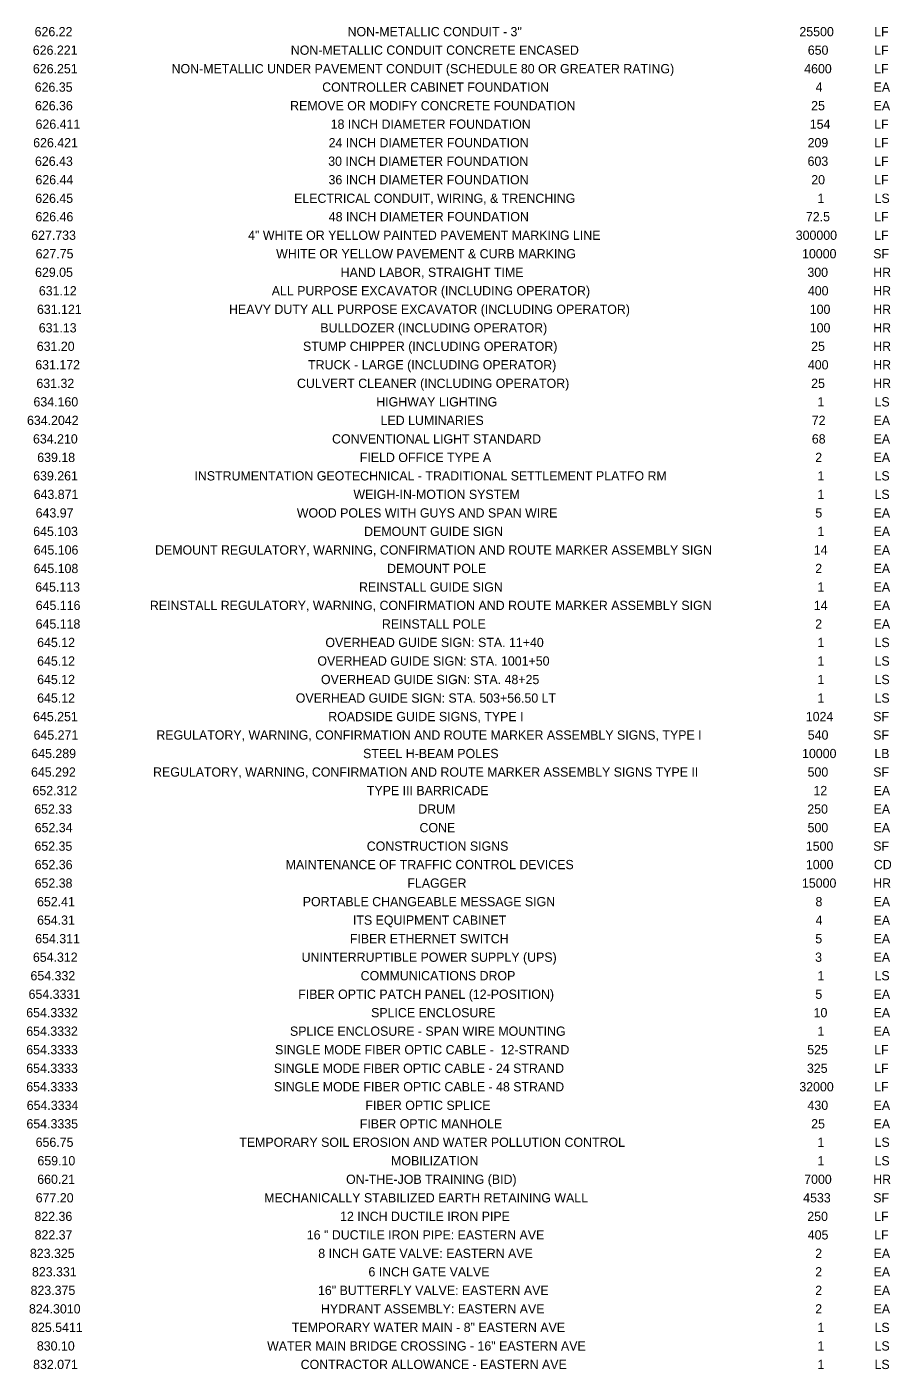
# Model space of a CAD drawing. Extents: x -18.7 to 5.6, y -2.7 to 4.
# Drawn here: x -18.677 to -17.757, y -1.71 to -0.282 of the extents above; entities that cross this region are included whole.
import ezdxf

# ---------------------------------------------------------------- set-up
doc = ezdxf.new("R2010")
doc.units = 0
doc.layers.add('ANNOTATION', color=7, linetype='Continuous')

msp = doc.modelspace()

# ---------------------------------------------------------------- texts
at = {"layer": 'ANNOTATION'}
for s, height, p in [('626.22', 0.00984, (-18.6685, -0.2925)), ('NON-METALLIC CONDUIT - 3"', 0.009843, (-18.3356, -0.2925)), ('25500', 0.00984, (-17.855, -0.2925)), ('LF', 0.00984, (-17.7755, -0.2925)), ('626.221', 0.00984, (-18.6704, -0.3122)), ('NON-METALLIC CONDUIT CONCRETE ENCASED', 0.009843, (-18.396, -0.3122)), ('650', 0.00984, (-17.8461, -0.3122)), ('LF', 0.00984, (-17.7755, -0.3122)), ('626.251', 0.00984, (-18.6703, -0.3319)), ('NON-METALLIC UNDER PAVEMENT CONDUIT (SCHEDULE 80 OR GREATER RATING)', 0.009843, (-18.5228, -0.3319)), ('4600', 0.00984, (-17.8499, -0.3319)), ('LF', 0.00984, (-17.7755, -0.3319)), ('626.35', 0.00984, (-18.6684, -0.3515)), ('CONTROLLER CABINET FOUNDATION', 0.009843, (-18.3626, -0.3515)), ('4', 0.00984, (-17.8378, -0.3515)), ('EA', 0.00984, (-17.7761, -0.3515)), ('626.36', 0.00984, (-18.6681, -0.3712)), ('REMOVE OR MODIFY CONCRETE FOUNDATION', 0.009843, (-18.3967, -0.3712)), ('25', 0.00984, (-17.8425, -0.3712)), ('EA', 0.00984, (-17.7761, -0.3712)), ('626.411', 0.00984, (-18.6675, -0.3909)), ('18 INCH DIAMETER FOUNDATION', 0.009843, (-18.3536, -0.3909)), ('154', 0.00984, (-17.844, -0.3909)), ('LF', 0.00984, (-17.7755, -0.3909)), ('626.421', 0.00984, (-18.67, -0.4106)), ('24 INCH DIAMETER FOUNDATION', 0.009843, (-18.3558, -0.4106)), ('209', 0.00984, (-17.8463, -0.4106)), ('LF', 0.00984, (-17.7755, -0.4106)), ('626.43', 0.00984, (-18.6681, -0.4303)), ('30 INCH DIAMETER FOUNDATION', 0.009843, (-18.3562, -0.4303)), ('603', 0.00984, (-17.8463, -0.4303)), ('LF', 0.00984, (-17.7755, -0.4303)), ('626.44', 0.00984, (-18.6676, -0.45)), ('36 INCH DIAMETER FOUNDATION', 0.009843, (-18.3559, -0.45)), ('20', 0.00984, (-17.8424, -0.45)), ('LF', 0.00984, (-17.7755, -0.45)), ('626.45', 0.00984, (-18.6678, -0.4697)), ('ELECTRICAL CONDUIT, WIRING, & TRENCHING', 0.009843, (-18.3925, -0.4697)), ('1', 0.00984, (-17.8358, -0.4697)), ('LS', 0.00984, (-17.7751, -0.4697)), ('626.46', 0.00984, (-18.6676, -0.4893)), ('48 INCH DIAMETER FOUNDATION', 0.009843, (-18.3556, -0.4893)), ('72.5', 0.00984, (-17.8481, -0.4893)), ('LF', 0.00984, (-17.7755, -0.4893)), ('627.733', 0.00984, (-18.6721, -0.509)), ('4" WHITE OR YELLOW PAINTED PAVEMENT MARKING LINE', 0.009843, (-18.4414, -0.509)), ('300000', 0.00984, (-17.8589, -0.509)), ('LF', 0.00984, (-17.7755, -0.509)), ('627.75', 0.00984, (-18.6674, -0.5287)), ('WHITE OR YELLOW PAVEMENT & CURB MARKING', 0.009843, (-18.4116, -0.5287)), ('10000', 0.00984, (-17.8522, -0.5287)), ('SF', 0.00984, (-17.7765, -0.5287)), ('629.05', 0.00984, (-18.668, -0.5484)), ('HAND LABOR, STRAIGHT TIME', 0.009843, (-18.343, -0.5484)), ('300', 0.00984, (-17.8465, -0.5484)), ('HR', 0.00984, (-17.7765, -0.5484)), ('631.12', 0.00984, (-18.664, -0.5681)), ('ALL PURPOSE EXCAVATOR (INCLUDING OPERATOR)', 0.009843, (-18.4163, -0.5681)), ('400', 0.00984, (-17.846, -0.5681)), ('HR', 0.00984, (-17.7765, -0.5681)), ('631.121', 0.00984, (-18.666, -0.5878)), ('HEAVY DUTY ALL PURPOSE EXCAVATOR (INCLUDING OPERATOR)', 0.009843, (-18.4617, -0.5878)), ('100', 0.00984, (-17.844, -0.5878)), ('HR', 0.00984, (-17.7765, -0.5878)), ('631.13', 0.00984, (-18.6641, -0.6075)), ('BULLDOZER (INCLUDING OPERATOR)', 0.009843, (-18.3646, -0.6075)), ('100', 0.00984, (-17.844, -0.6075)), ('HR', 0.00984, (-17.7765, -0.6075)), ('631.20', 0.00984, (-18.6662, -0.6271)), ('STUMP CHIPPER (INCLUDING OPERATOR)', 0.009843, (-18.383, -0.6271)), ('25', 0.00984, (-17.8425, -0.6271)), ('HR', 0.00984, (-17.7765, -0.6271)), ('631.172', 0.00984, (-18.6678, -0.6468)), ('TRUCK - LARGE (INCLUDING OPERATOR)', 0.009843, (-18.3776, -0.6468)), ('400', 0.00984, (-17.846, -0.6468)), ('HR', 0.00984, (-17.7765, -0.6468)), ('631.32', 0.00984, (-18.6666, -0.6665)), ('CULVERT CLEANER (INCLUDING OPERATOR)', 0.009843, (-18.3894, -0.6665)), ('25', 0.00984, (-17.8425, -0.6665)), ('HR', 0.00984, (-17.7765, -0.6665)), ('634.160', 0.00984, (-18.6697, -0.6862)), ('HIGHWAY LIGHTING', 0.009843, (-18.3051, -0.6862)), ('1', 0.00984, (-17.8358, -0.6862)), ('LS', 0.00984, (-17.7751, -0.6862)), ('634.2042', 0.00984, (-18.6766, -0.7059)), ('LED LUMINARIES', 0.009843, (-18.3005, -0.7059)), ('72', 0.00984, (-17.8419, -0.7059)), ('EA', 0.00984, (-17.7761, -0.7059)), ('634.210', 0.00984, (-18.6702, -0.7256)), ('CONVENTIONAL LIGHT STANDARD', 0.009843, (-18.3521, -0.7256)), ('68', 0.00984, (-17.8418, -0.7256)), ('EA', 0.00984, (-17.7761, -0.7256)), ('639.18', 0.00984, (-18.6657, -0.7453)), ('FIELD OFFICE TYPE A', 0.009843, (-18.3226, -0.7453)), ('2', 0.00984, (-17.8382, -0.7453)), ('EA', 0.00984, (-17.7761, -0.7453)), ('639.261', 0.00984, (-18.67, -0.7649)), ('INSTRUMENTATION GEOTECHNICAL - TRADITIONAL SETTLEMENT PLATFO RM', 0.009843, (-18.4985, -0.7649)), ('1', 0.00984, (-17.8358, -0.7649)), ('LS', 0.00984, (-17.7751, -0.7649)), ('643.871', 0.00984, (-18.6695, -0.7846)), ('WEIGH-IN-MOTION SYSTEM', 0.009843, (-18.3294, -0.7846)), ('1', 0.00984, (-17.8358, -0.7846)), ('LS', 0.00984, (-17.7751, -0.7846)), ('643.97', 0.00984, (-18.6674, -0.8043)), ('WOOD POLES WITH GUYS AND SPAN WIRE', 0.009843, (-18.3896, -0.8043)), ('5', 0.00984, (-17.8381, -0.8043)), ('EA', 0.00984, (-17.7761, -0.8043)), ('645.103', 0.00984, (-18.67, -0.824)), ('DEMOUNT GUIDE SIGN', 0.009843, (-18.318, -0.824)), ('1', 0.00984, (-17.8358, -0.824)), ('EA', 0.00984, (-17.7761, -0.824)), ('645.106', 0.00984, (-18.6695, -0.8437)), ('DEMOUNT REGULATORY, WARNING, CONFIRMATION AND ROUTE MARKER ASSEMBLY SIGN', 0.009843, (-18.5404, -0.8437)), ('14', 0.00984, (-17.8397, -0.8437)), ('EA', 0.00984, (-17.7761, -0.8437)), ('645.108', 0.00984, (-18.6696, -0.8634)), ('DEMOUNT POLE', 0.009843, (-18.2936, -0.8634)), ('2', 0.00984, (-17.8382, -0.8634)), ('EA', 0.00984, (-17.7761, -0.8634)), ('645.113', 0.00984, (-18.6678, -0.8831)), ('REINSTALL GUIDE SIGN', 0.009843, (-18.3234, -0.8831)), ('1', 0.00984, (-17.8358, -0.8831)), ('EA', 0.00984, (-17.7761, -0.8831)), ('645.116', 0.00984, (-18.6673, -0.9027)), ('REINSTALL REGULATORY, WARNING, CONFIRMATION AND ROUTE MARKER ASSEMBLY SIGN', 0.009843, (-18.5459, -0.9027)), ('14', 0.00984, (-17.8397, -0.9027)), ('EA', 0.00984, (-17.7761, -0.9027)), ('645.118', 0.00984, (-18.6674, -0.9224)), ('REINSTALL POLE', 0.009843, (-18.2991, -0.9224)), ('2', 0.00984, (-17.8382, -0.9224)), ('EA', 0.00984, (-17.7761, -0.9224)), ('645.12', 0.00984, (-18.6658, -0.9421)), ('OVERHEAD GUIDE SIGN: STA. 11+40', 0.009843, (-18.3592, -0.9421)), ('1', 0.00984, (-17.8358, -0.9421)), ('LS', 0.00984, (-17.7751, -0.9421)), ('645.12', 0.00984, (-18.6658, -0.9618)), ('OVERHEAD GUIDE SIGN: STA. 1001+50', 0.009843, (-18.3677, -0.9618)), ('1', 0.00984, (-17.8358, -0.9618)), ('LS', 0.00984, (-17.7751, -0.9618)), ('645.12', 0.00984, (-18.6658, -0.9815)), ('OVERHEAD GUIDE SIGN: STA. 48+25', 0.009843, (-18.3639, -0.9815)), ('1', 0.00984, (-17.8358, -0.9815)), ('LS', 0.00984, (-17.7751, -0.9815)), ('645.12', 0.00984, (-18.6658, -1.0012)), ('OVERHEAD GUIDE SIGN: STA. 503+56.50 LT', 0.009843, (-18.3907, -1.0012)), ('1', 0.00984, (-17.8358, -1.0012)), ('LS', 0.00984, (-17.7751, -1.0012)), ('645.251', 0.00984, (-18.6701, -1.0209)), ('ROADSIDE GUIDE SIGNS, TYPE I', 0.009843, (-18.3562, -1.0209)), ('1024', 0.00984, (-17.8482, -1.0209)), ('SF', 0.00984, (-17.7765, -1.0209)), ('645.271', 0.00984, (-18.6696, -1.0405)), ('REGULATORY, WARNING, CONFIRMATION AND ROUTE MARKER ASSEMBLY SIGNS, TYPE I', 0.009843, (-18.539, -1.0405)), ('540', 0.00984, (-17.8461, -1.0405)), ('SF', 0.00984, (-17.7765, -1.0405)), ('645.289', 0.00984, (-18.672, -1.0602)), ('STEEL H-BEAM POLES', 0.009843, (-18.3191, -1.0602)), ('10000', 0.00984, (-17.8522, -1.0602)), ('LB', 0.00984, (-17.7753, -1.0602)), ('645.292', 0.00984, (-18.6723, -1.0799)), ('REGULATORY, WARNING, CONFIRMATION AND ROUTE MARKER ASSEMBLY SIGNS TYPE II', 0.009843, (-18.5425, -1.0799)), ('500', 0.00984, (-17.8463, -1.0799)), ('SF', 0.00984, (-17.7765, -1.0799)), ('652.312', 0.00984, (-18.6708, -1.0996)), ('TYPE III BARRICADE', 0.009843, (-18.3151, -1.0996)), ('12', 0.00984, (-17.8401, -1.0996)), ('EA', 0.00984, (-17.7761, -1.0996)), ('652.33', 0.00984, (-18.6689, -1.1193)), ('DRUM', 0.00984, (-18.2604, -1.1193)), ('250', 0.00984, (-17.8466, -1.1193)), ('EA', 0.00984, (-17.7761, -1.1193)), ('652.34', 0.00984, (-18.6684, -1.139)), ('CONE', 0.00984, (-18.2591, -1.139)), ('500', 0.00984, (-17.8463, -1.139)), ('EA', 0.00984, (-17.7761, -1.139)), ('652.35', 0.00984, (-18.6687, -1.1587)), ('CONSTRUCTION SIGNS', 0.009843, (-18.3152, -1.1587)), ('1500', 0.00984, (-17.8482, -1.1587)), ('SF', 0.00984, (-17.7765, -1.1587)), ('652.36', 0.00984, (-18.6684, -1.1783)), ('MAINTENANCE OF TRAFFIC CONTROL DEVICES', 0.009843, (-18.4015, -1.1783)), ('1000', 0.00984, (-17.8481, -1.1783)), ('CD', 0.00984, (-17.7758, -1.1783)), ('652.38', 0.00984, (-18.6685, -1.198)), ('FLAGGER', 0.00984, (-18.272, -1.198)), ('15000', 0.00984, (-17.8523, -1.198)), ('HR', 0.00984, (-17.7765, -1.198)), ('652.41', 0.00984, (-18.6659, -1.2177)), ('PORTABLE CHANGEABLE MESSAGE SIGN', 0.009843, (-18.3833, -1.2177)), ('8', 0.00984, (-17.8379, -1.2177)), ('EA', 0.00984, (-17.7761, -1.2177)), ('654.31', 0.00984, (-18.6659, -1.2374)), ('ITS EQUIPMENT CABINET  ', 0.009843, (-18.3299, -1.2374)), ('4', 0.00984, (-17.8378, -1.2374)), ('EA', 0.00984, (-17.7761, -1.2374)), ('654.311', 0.00984, (-18.6679, -1.2571)), ('FIBER ETHERNET SWITCH ', 0.009843, (-18.3332, -1.2571)), ('5', 0.00984, (-17.8381, -1.2571)), ('EA', 0.00984, (-17.7761, -1.2571)), ('654.312', 0.00984, (-18.6703, -1.2768)), ('UNINTERRUPTIBLE POWER SUPPLY (UPS)', 0.009843, (-18.3845, -1.2768)), ('3', 0.00984, (-17.8383, -1.2768)), ('EA', 0.00984, (-17.7761, -1.2768)), ('654.332', 0.00984, (-18.6729, -1.2965)), ('COMMUNICATIONS DROP', 0.009843, (-18.3217, -1.2965)), ('1', 0.00984, (-17.8358, -1.2965)), ('LS', 0.00984, (-17.7751, -1.2965)), ('654.3331', 0.00984, (-18.6749, -1.3162)), ('FIBER OPTIC PATCH PANEL (12-POSITION)', 0.009843, (-18.3881, -1.3162)), ('5', 0.00984, (-17.8381, -1.3162)), ('EA', 0.00984, (-17.7761, -1.3162)), ('654.3332', 0.00984, (-18.6774, -1.3358)), ('SPLICE ENCLOSURE', 0.009843, (-18.3106, -1.3358)), ('10', 0.00984, (-17.8399, -1.3358)), ('EA', 0.00984, (-17.7761, -1.3358)), ('654.3332', 0.00984, (-18.6774, -1.3555)), ('SPLICE ENCLOSURE - SPAN WIRE MOUNTING', 0.009843, (-18.3969, -1.3555)), ('1', 0.00984, (-17.8358, -1.3555)), ('EA', 0.00984, (-17.7761, -1.3555)), ('654.3333', 0.00984, (-18.6774, -1.3752)), ('SINGLE MODE FIBER OPTIC CABLE -  12-STRAND', 0.009843, (-18.4127, -1.3752)), ('525', 0.00984, (-17.8467, -1.3752)), ('LF', 0.00984, (-17.7755, -1.3752)), ('654.3333', 0.00984, (-18.6774, -1.3949)), ('SINGLE MODE FIBER OPTIC CABLE - 24 STRAND', 0.009843, (-18.414, -1.3949)), ('325', 0.00984, (-17.847, -1.3949)), ('LF', 0.00984, (-17.7755, -1.3949)), ('654.3333', 0.00984, (-18.6774, -1.4146)), ('SINGLE MODE FIBER OPTIC CABLE - 48 STRAND', 0.009843, (-18.4139, -1.4146)), ('32000', 0.00984, (-17.8551, -1.4146)), ('LF', 0.00984, (-17.7755, -1.4146)), ('654.3334', 0.00984, (-18.6769, -1.4343)), ('FIBER OPTIC SPLICE ', 0.009843, (-18.3167, -1.4343)), ('430', 0.00984, (-17.8464, -1.4343)), ('EA', 0.00984, (-17.7761, -1.4343)), ('654.3335', 0.00984, (-18.6772, -1.454)), ('FIBER OPTIC MANHOLE ', 0.009843, (-18.3226, -1.454)), ('25', 0.00984, (-17.8425, -1.454)), ('EA', 0.00984, (-17.7761, -1.454)), ('656.75', 0.00984, (-18.6674, -1.4736)), ('TEMPORARY SOIL EROSION AND WATER POLLUTION CONTROL', 0.009843, (-18.4508, -1.4736)), ('1', 0.00984, (-17.8358, -1.4736)), ('LS', 0.00984, (-17.7751, -1.4736)), ('659.10', 0.00984, (-18.6655, -1.4933)), ('MOBILIZATION', 0.009843, (-18.2893, -1.4933)), ('1', 0.00984, (-17.8358, -1.4933)), ('LS', 0.00984, (-17.7751, -1.4933)), ('660.21', 0.00984, (-18.6657, -1.513)), ('ON-THE-JOB TRAINING (BID)', 0.009843, (-18.3372, -1.513)), ('7000', 0.00984, (-17.8499, -1.513)), ('HR', 0.00984, (-17.7765, -1.513)), ('677.20', 0.00984, (-18.6673, -1.5327)), ('MECHANICALLY STABILIZED EARTH RETAINING WALL', 0.009843, (-18.4243, -1.5327)), ('4533', 0.00984, (-17.851, -1.5327)), ('SF', 0.00984, (-17.7765, -1.5327)), ('822.36', 0.00984, (-18.6687, -1.5524)), ('12 INCH DUCTILE IRON PIPE', 0.009843, (-18.3436, -1.5524)), ('250', 0.00984, (-17.8466, -1.5524)), ('LF', 0.00984, (-17.7755, -1.5524)), ('822.37', 0.00984, (-18.6685, -1.5721)), ('16 " DUCTILE IRON PIPE: EASTERN AVE', 0.009843, (-18.379, -1.5721)), ('405', 0.00984, (-17.8461, -1.5721)), ('LF', 0.00984, (-17.7755, -1.5721)), ('823.325', 0.00984, (-18.6735, -1.5918)), ('8 INCH GATE VALVE: EASTERN AVE', 0.009843, (-18.3668, -1.5918)), ('2', 0.00984, (-17.8382, -1.5918)), ('EA', 0.00984, (-17.7761, -1.5918)), ('823.331', 0.00984, (-18.6713, -1.6114)), ('6 INCH GATE VALVE', 0.009843, (-18.3134, -1.6114)), ('2', 0.00984, (-17.8382, -1.6114)), ('EA', 0.00984, (-17.7761, -1.6114)), ('823.375', 0.00984, (-18.6728, -1.6311)), ('16" BUTTERFLY VALVE: EASTERN AVE', 0.009843, (-18.3671, -1.6311)), ('2', 0.00984, (-17.8382, -1.6311)), ('EA', 0.00984, (-17.7761, -1.6311)), ('824.3010', 0.00984, (-18.6745, -1.6508)), ('HYDRANT ASSEMBLY: EASTERN AVE', 0.009843, (-18.3639, -1.6508)), ('2', 0.00984, (-17.8382, -1.6508)), ('EA', 0.00984, (-17.7761, -1.6508)), ('825.5411', 0.00984, (-18.6722, -1.6705)), ('TEMPORARY WATER MAIN - 8" EASTERN AVE', 0.009843, (-18.3949, -1.6705)), ('1', 0.00984, (-17.8358, -1.6705)), ('LS', 0.00984, (-17.7751, -1.6705)), ('830.10', 0.00984, (-18.6661, -1.6902)), ('WATER MAIN BRIDGE CROSSING - 16" EASTERN AVE', 0.009843, (-18.4212, -1.6902)), ('1', 0.00984, (-17.8358, -1.6902)), ('LS', 0.00984, (-17.7751, -1.6902)), ('832.071', 0.00984, (-18.6701, -1.7099)), ('CONTRACTOR ALLOWANCE - EASTERN AVE', 0.009843, (-18.3855, -1.7099)), ('1', 0.00984, (-17.8358, -1.7099)), ('LS', 0.00984, (-17.7751, -1.7099))]:
    msp.add_text(s, height=height, dxfattribs=at).set_placement(p)

doc.saveas('drawing.dxf')
